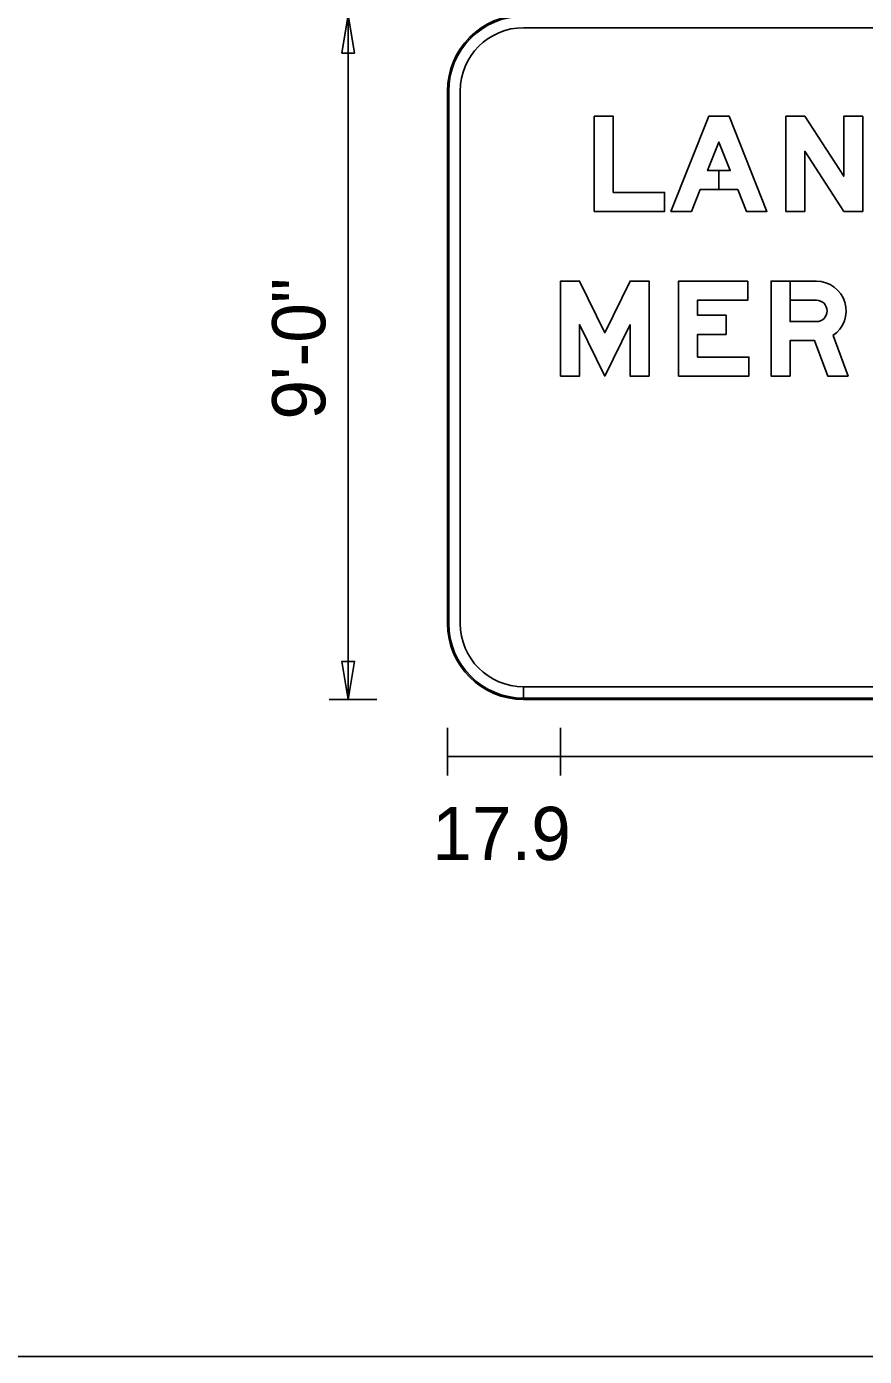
# Model space of a CAD drawing. Extents: x 10268147 to 10268469, y 2141099 to 2141204.
# Drawn here: x 10268190.55 to 10268201.56, y 2141130.4 to 2141147.88 of the extents above; entities that cross this region are included whole.
import ezdxf

# ---------------------------------------------------------------- set-up
doc = ezdxf.new("R2010")
doc.units = 0
for name, color, linetype in [('61', 7, 'Continuous'), ('GSDims', 7, 'Continuous'), ('PlotBorder_dp', 7, 'Continuous')]:
    doc.layers.add(name, color=color, linetype=linetype)

msp = doc.modelspace()

# ---------------------------------------------------------------- linework, layer by layer
at = {"layer": '61'}
msp.add_line((10268153.875, 2141130.399), (10268229.209, 2141130.399), dxfattribs=at)
at = {"layer": 'GSDims'}
for p, q in [((10268194.776, 2141139.037), (10268194.776, 2141148.037)), ((10268195.151, 2141139.037), (10268194.526, 2141139.037)), ((10268196.081, 2141138.662), (10268196.081, 2141138.037)), ((10268197.568, 2141138.662), (10268197.568, 2141138.037)), ((10268197.568, 2141138.662), (10268197.568, 2141138.037)), ((10268196.081, 2141138.287), (10268197.568, 2141138.287)), ((10268197.568, 2141138.287), (10268210.093, 2141138.287))]:
    msp.add_line(p, q, dxfattribs=at)
for points in [[(10268194.776, 2141148.037), (10268194.859, 2141147.537), (10268194.693, 2141147.537)], [(10268194.776, 2141139.037), (10268194.859, 2141139.537), (10268194.693, 2141139.537)]]:
    msp.add_lwpolyline(points, close=True, dxfattribs=at)
at = {"layer": 'PlotBorder_dp'}
for p, q in [((10268197.081, 2141147.87), (10268210.581, 2141147.87)), ((10268197.081, 2141147.87), (10268210.581, 2141147.87)), ((10268196.081, 2141147.037), (10268196.081, 2141140.037)), ((10268196.081, 2141147.037), (10268196.081, 2141140.037)), ((10268196.081, 2141147.037), (10268196.081, 2141140.037)), ((10268196.081, 2141147.037), (10268196.081, 2141140.037)), ((10268196.097, 2141140.037), (10268196.097, 2141147.037)), ((10268196.247, 2141140.037), (10268196.247, 2141147.037)), ((10268196.247, 2141140.037), (10268196.247, 2141147.037)), ((10268197.081, 2141139.037), (10268197.081, 2141139.204)), ((10268197.081, 2141139.037), (10268197.081, 2141139.204)), ((10268210.581, 2141139.204), (10268197.082, 2141139.204)), ((10268197.082, 2141139.204), (10268197.082, 2141139.037)), ((10268210.581, 2141139.204), (10268197.082, 2141139.204)), ((10268197.082, 2141139.204), (10268197.082, 2141139.037)), ((10268197.081, 2141139.037), (10268197.081, 2141139.054)), ((10268210.581, 2141139.054), (10268197.081, 2141139.054)), ((10268197.081, 2141139.054), (10268197.081, 2141139.037)), ((10268197.081, 2141139.037), (10268210.581, 2141139.037)), ((10268197.081, 2141139.037), (10268210.581, 2141139.037)), ((10268197.082, 2141139.037), (10268210.581, 2141139.037)), ((10268197.082, 2141139.037), (10268210.581, 2141139.037))]:
    msp.add_line(p, q, dxfattribs=at)
for points in [[(10268198.261, 2141145.705), (10268198.936, 2141145.705), (10268198.936, 2141145.455), (10268198.011, 2141145.455), (10268198.011, 2141146.705), (10268198.261, 2141146.705)], [(10268198.261, 2141145.705), (10268198.936, 2141145.705), (10268198.936, 2141145.455), (10268198.011, 2141145.455), (10268198.011, 2141146.705), (10268198.261, 2141146.705)], [(10268198.261, 2141145.705), (10268198.936, 2141145.705), (10268198.936, 2141145.455), (10268198.011, 2141145.455), (10268198.011, 2141146.705), (10268198.261, 2141146.705)], [(10268199.897, 2141145.742), (10268199.401, 2141145.742), (10268199.287, 2141145.455), (10268199.018, 2141145.455), (10268199.515, 2141146.705), (10268199.784, 2141146.705), (10268200.281, 2141145.455), (10268200.011, 2141145.455)], [(10268199.649, 2141145.992), (10268199.649, 2141145.742), (10268199.401, 2141145.742), (10268199.287, 2141145.455), (10268199.018, 2141145.455), (10268199.515, 2141146.705), (10268199.784, 2141146.705), (10268200.281, 2141145.455), (10268200.011, 2141145.455), (10268199.897, 2141145.742), (10268199.649, 2141145.742), (10268199.649, 2141145.992), (10268199.798, 2141145.992), (10268199.649, 2141146.366), (10268199.501, 2141145.992)], [(10268199.649, 2141145.992), (10268199.649, 2141145.742), (10268199.401, 2141145.742), (10268199.287, 2141145.455), (10268199.018, 2141145.455), (10268199.515, 2141146.705), (10268199.784, 2141146.705), (10268200.281, 2141145.455), (10268200.011, 2141145.455), (10268199.897, 2141145.742), (10268199.649, 2141145.742), (10268199.649, 2141145.992), (10268199.798, 2141145.992), (10268199.649, 2141146.366), (10268199.501, 2141145.992)], [(10268200.528, 2141146.705), (10268200.778, 2141146.705), (10268201.291, 2141145.917), (10268201.291, 2141146.705), (10268201.541, 2141146.705), (10268201.541, 2141145.455), (10268201.293, 2141145.455), (10268200.778, 2141146.246), (10268200.778, 2141145.455), (10268200.528, 2141145.455)], [(10268200.528, 2141146.705), (10268200.778, 2141146.705), (10268201.291, 2141145.917), (10268201.291, 2141146.705), (10268201.541, 2141146.705), (10268201.541, 2141145.455), (10268201.293, 2141145.455), (10268200.778, 2141146.246), (10268200.778, 2141145.455), (10268200.528, 2141145.455)], [(10268200.528, 2141146.705), (10268200.778, 2141146.705), (10268201.291, 2141145.917), (10268201.291, 2141146.705), (10268201.541, 2141146.705), (10268201.541, 2141145.455), (10268201.293, 2141145.455), (10268200.778, 2141146.246), (10268200.778, 2141145.455), (10268200.528, 2141145.455)], [(10268199.501, 2141145.992), (10268199.798, 2141145.992), (10268199.649, 2141146.366)], [(10268198.481, 2141143.967), (10268198.481, 2141143.288), (10268198.731, 2141143.288), (10268198.731, 2141144.538), (10268198.481, 2141144.538), (10268198.149, 2141143.858), (10268197.818, 2141144.538), (10268197.568, 2141144.538), (10268197.568, 2141143.288), (10268197.818, 2141143.288), (10268197.818, 2141143.967), (10268198.149, 2141143.288)], [(10268198.481, 2141143.967), (10268198.481, 2141143.288), (10268198.731, 2141143.288), (10268198.731, 2141144.538), (10268198.481, 2141144.538), (10268198.149, 2141143.858), (10268197.818, 2141144.538), (10268197.568, 2141144.538), (10268197.568, 2141143.288), (10268197.818, 2141143.288), (10268197.818, 2141143.967), (10268198.149, 2141143.288)], [(10268198.481, 2141143.967), (10268198.481, 2141143.288), (10268198.731, 2141143.288), (10268198.731, 2141144.538), (10268198.481, 2141144.538), (10268198.149, 2141143.858), (10268197.818, 2141144.538), (10268197.568, 2141144.538), (10268197.568, 2141143.288), (10268197.818, 2141143.288), (10268197.818, 2141143.967), (10268198.149, 2141143.288)], [(10268200.031, 2141144.538), (10268200.031, 2141144.288), (10268199.369, 2141144.288), (10268199.369, 2141144.088), (10268199.744, 2141144.088), (10268199.744, 2141143.838), (10268199.369, 2141143.838), (10268199.369, 2141143.538), (10268200.044, 2141143.538), (10268200.044, 2141143.288), (10268199.119, 2141143.288), (10268199.119, 2141144.538)], [(10268200.031, 2141144.538), (10268200.031, 2141144.288), (10268199.369, 2141144.288), (10268199.369, 2141144.088), (10268199.744, 2141144.088), (10268199.744, 2141143.838), (10268199.369, 2141143.838), (10268199.369, 2141143.538), (10268200.044, 2141143.538), (10268200.044, 2141143.288), (10268199.119, 2141143.288), (10268199.119, 2141144.538)], [(10268200.031, 2141144.538), (10268200.031, 2141144.288), (10268199.369, 2141144.288), (10268199.369, 2141144.088), (10268199.744, 2141144.088), (10268199.744, 2141143.838), (10268199.369, 2141143.838), (10268199.369, 2141143.538), (10268200.044, 2141143.538), (10268200.044, 2141143.288), (10268199.119, 2141143.288), (10268199.119, 2141144.538)]]:
    msp.add_lwpolyline(points, close=True, dxfattribs=at)
for points in [[(10268201.149, 2141143.821), (10268201.347, 2141143.288), (10268201.08, 2141143.288), (10268200.907, 2141143.755), (10268200.585, 2141143.755), (10268200.585, 2141143.288), (10268200.335, 2141143.288), (10268200.335, 2141144.538), (10268200.585, 2141144.538), (10268200.585, 2141144.005)], [(10268201.149, 2141143.821), (10268201.347, 2141143.288), (10268201.08, 2141143.288), (10268200.907, 2141143.755), (10268200.585, 2141143.755), (10268200.585, 2141143.288), (10268200.335, 2141143.288), (10268200.335, 2141144.538), (10268200.585, 2141144.538), (10268200.585, 2141144.005)], [(10268201.149, 2141143.821), (10268201.347, 2141143.288), (10268201.08, 2141143.288), (10268200.907, 2141143.755), (10268200.585, 2141143.755), (10268200.585, 2141143.288), (10268200.335, 2141143.288), (10268200.335, 2141144.538), (10268200.931, 2141144.538)], [(10268200.931, 2141144.288), (10268200.585, 2141144.288), (10268200.585, 2141144.538), (10268200.931, 2141144.538)], [(10268200.931, 2141144.288), (10268200.585, 2141144.288), (10268200.585, 2141144.538), (10268200.931, 2141144.538)], [(10268200.931, 2141144.005), (10268200.585, 2141144.005), (10268200.585, 2141144.288), (10268200.931, 2141144.288)], [(10268200.585, 2141144.005), (10268200.931, 2141144.005)], [(10268200.585, 2141144.005), (10268200.931, 2141144.005)]]:
    msp.add_lwpolyline(points, dxfattribs=at)
for centre, radius, start, end in [((10268197.081, 2141147.037), 1, 90, 180), ((10268197.081, 2141147.037), 1, 90, 180), ((10268197.081, 2141147.037), 1, 90, 180), ((10268197.081, 2141147.037), 1, 90, 180), ((10268197.081, 2141147.037), 0.983, 90, 180), ((10268197.081, 2141147.037), 0.833, 90, 180), ((10268197.081, 2141147.037), 0.833, 90, 180), ((10268197.081, 2141140.037), 1, 180, 270), ((10268197.081, 2141140.037), 1, 180, 270), ((10268197.081, 2141140.037), 1, 180, 270), ((10268197.081, 2141140.037), 1, 180, 270), ((10268197.081, 2141140.037), 0.983, 180, 270), ((10268197.081, 2141140.037), 0.833, 180, 270), ((10268197.081, 2141140.037), 0.833, 180, 270)]:
    msp.add_arc(centre, radius, start, end, dxfattribs=at)
for major_axis, start_param in [((0, 0.391), 3.731228), ((0, 0.391), 3.731228), ((0, 0.391), 3.731228), ((0, 0.141), 3.141593), ((0, 0.141), 3.141593), ((0, 0.141), 3.141593)]:
    msp.add_ellipse((10268200.931, 2141144.146), major_axis=major_axis, ratio=0.999996, start_param=start_param, end_param=6.283185, dxfattribs=at)

# ---------------------------------------------------------------- texts
at = {"layer": 'GSDims'}
msp.add_text('9\'-0"', height=0.7, rotation=90, dxfattribs=at).set_placement((10268194.476, 2141142.717))
msp.add_text('17.9', height=0.7, dxfattribs=at).set_placement((10268195.881, 2141136.925))

doc.saveas('drawing.dxf')
